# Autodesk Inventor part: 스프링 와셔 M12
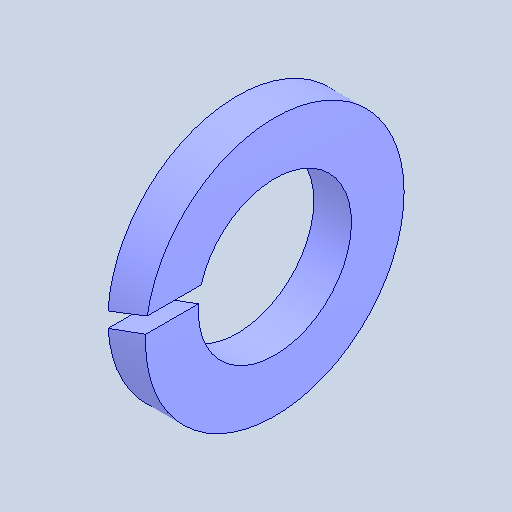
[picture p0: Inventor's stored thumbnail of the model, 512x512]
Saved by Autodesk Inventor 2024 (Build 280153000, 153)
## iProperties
Created: 2024-08
Part Number: 스프링 와셔 M12
Material: 강철, 연강
Description: 스프링 잠금 와셔
Document SubType Name: Modeling
Designer: user
Density: 7.85 g/cm^3
Appearance: 기본값
Author: jhkim
Sending System: Autodesk Inventor 2025
Preprocessor: ST-DEVELOPER v20
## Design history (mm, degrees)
feature "Solid1"
node "솔리드1"
